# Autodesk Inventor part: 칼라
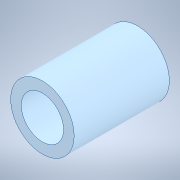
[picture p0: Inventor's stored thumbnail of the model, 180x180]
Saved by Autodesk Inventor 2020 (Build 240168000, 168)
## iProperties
Created: 2024-04
Part Number: 칼라
Material: 강철, 탄소
Document SubType Name: Modeling
Designer: oem
Density: 7.87 g/cm^3
Appearance: 기본값
Author: jhkim
Sending System: Autodesk Inventor 2025
Preprocessor: ST-DEVELOPER v20
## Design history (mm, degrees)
feature "솔리드1"
node "솔리드2"
